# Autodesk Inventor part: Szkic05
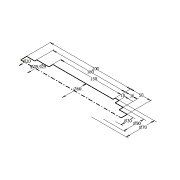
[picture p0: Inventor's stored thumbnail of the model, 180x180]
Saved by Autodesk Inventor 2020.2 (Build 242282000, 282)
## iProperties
Created: 2005-01
Part Number: Szkic05
Document SubType Name: Modeling
Designer: F.Stasiak
Manufacturer: Standard
Standards Organization: Custom
Density: 1 g/cm^3
Material: Ogólny
Appearance: Domyślna
Manager: www.cadconsulting.pl
Company: Fabian Stasiak CAD Consulting
Author: F.Stasiak
Subject: Zbiór ćwiczeń. Autodesk Inventor 2020. Kurs podstawowy
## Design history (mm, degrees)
sketch "Szkic1"
  geometry: L1 (0, 0)-(0, 15); L2 (0, 15)-(20, 15); L3 (20, 15)-(20, 19.965); L4 (20, 19.965)-(50, 19.965); L5 (50, 19.965)-(50, 30); L6 (50, 30)-(200, 30); L7 (200, 30)-(200, 35); L8 (200, 35)-(210, 35); L9 (210, 35)-(210, 25); L10 (210, 25)-(230, 25); L11 (230, 25)-(230, 15); L12 (230, 15)-(250, 15); L13 (250, 15)-(250, 0); L14 (0, 0)-(250, 0); 1 further point
  constraints: 28 end point, 10 parallel, 2 perpendicular, 1 coincident, 1 collinear, 1 vertical
  dimensions: "d31" = 10 distance of L7.end L8.end; "d32" = 150 distance of L5.end L6.end; "d33" = 180 distance between parallel lines of L3 L7; "d34" = 200 distance between parallel lines of L1 L7; "d35" = 30 distance between parallel lines of L11 L7; "d37" = 50 distance between parallel lines of L13 L7; "d38" = 30 diameter of L12 L14; "d39" = 50 diameter of L10 L14; "d40" = 70 diameter of L8 L14; "d41" = 60 diameter of L6 L14; "d42" = 40 dimension on L4 L14; "d43" = 30 diameter of L2 L14
node "Korpusy bryłowe"
node "Korpusy powierzchniowe"
